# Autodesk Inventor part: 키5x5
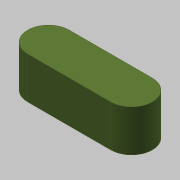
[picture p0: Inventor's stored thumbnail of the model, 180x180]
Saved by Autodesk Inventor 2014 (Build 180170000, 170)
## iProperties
Created: 2011-04
Part Number: 키5x5
Document SubType Name: Modeling
Designer: pww
Density: 7.86 g/cm^3
Material: 강철, 연강
Appearance: Olive Green
Author: pww
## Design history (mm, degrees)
sketch "스케치1"
  geometry: L1 (-5, -2.5)-(5, -2.5); L2 (5, 2.5)-(-5, 2.5); A1 r 2.5 centre (-5, 0) between (-5, 2.5) and (-5, -2.5); A2 r 2.5 centre (5, 0) between (5, -2.5) and (5, 2.5); 1 further point
  constraints: 4 end point, 4 point on circle, 2 centre point
extrude "돌출1" new body sketch "스케치1" distance "d0" = 5; taper "d1" = 0 deg
node "솔리드1"
